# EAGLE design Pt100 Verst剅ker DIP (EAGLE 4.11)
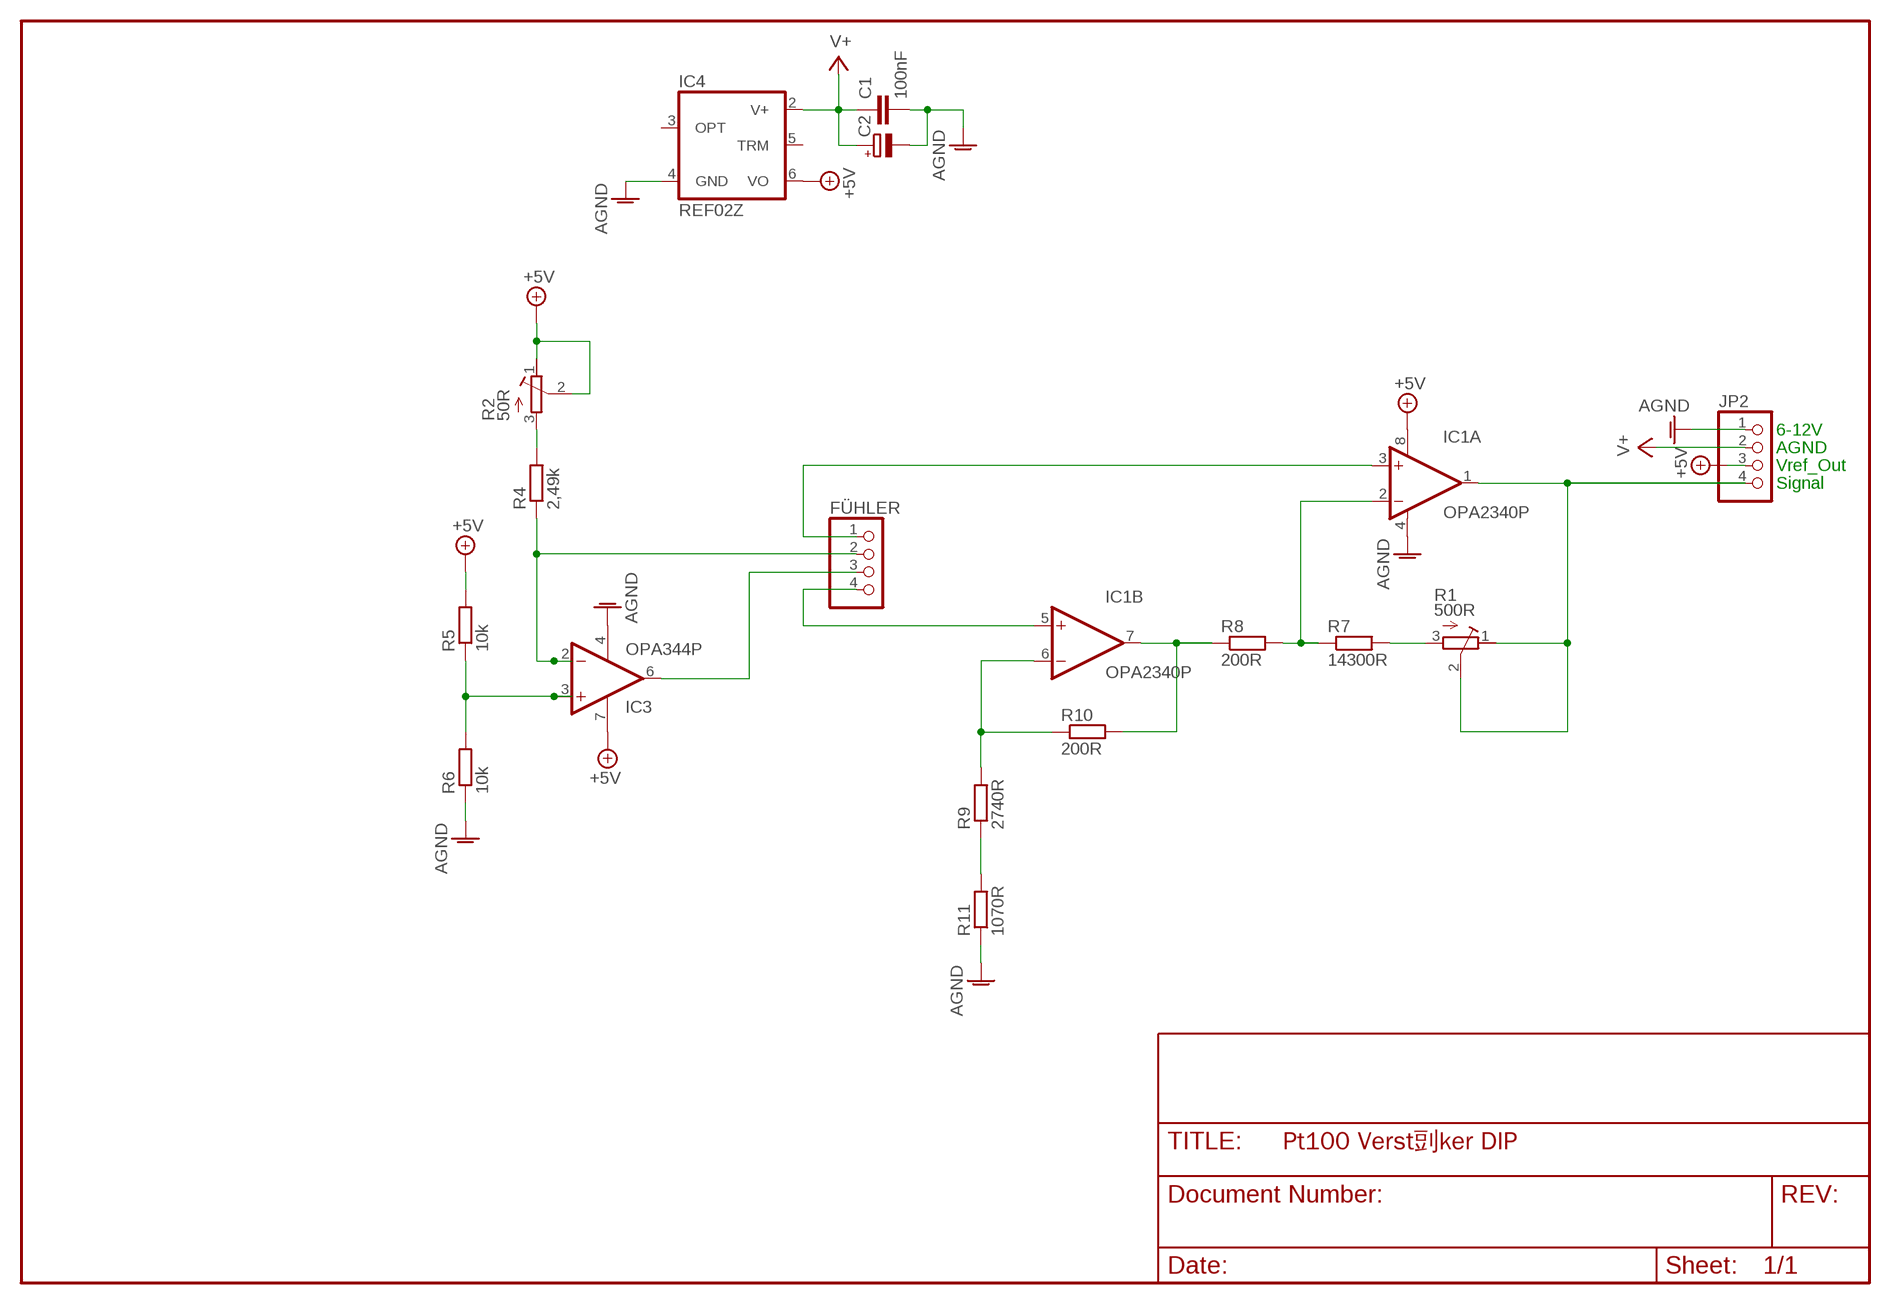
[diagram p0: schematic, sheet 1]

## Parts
C1  100nF  C-EU050-025X075  [C050-025X075]
C2  CPOL-EUE2-5  [E2-5]
FÜHLER  PINHD-1X4  [1X04]
IC1  OPA2340P  [DIL08]
IC3  OPA344P  [DIL08]
IC4  REF02Z  [DIL08]
JP2  PINHD-1X4  [1X04]
R1  500R  R-TRIMM43P  [RTRIM43P]
R2  50R  R-TRIMM43P  [RTRIM43P]
R4  2,49k  R-EU_0207/10  [0207/10]
R5  10k  R-EU_0207/10  [0207/10]
R6  10k  R-EU_0207/10  [0207/10]
R7  14300R  R-EU_0207/10  [0207/10]
R8  200R  R-EU_0207/10  [0207/10]
R9  2740R  R-EU_0207/10  [0207/10]
R10  200R  R-EU_0207/10  [0207/10]
R11  1070R  R-EU_0207/10  [0207/10]

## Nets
+5V: IC1.8(A:V+) IC3.7(V+) IC4.6(VO) JP2.3 R2.1(A) R2.2(S) R5.2
AGND: C1.2 C2.- IC1.4(A:V-) IC3.4(V-) IC4.4(GND) JP2.1 R6.1 R11.1
N$1: R2.3(E) R4.2
N$2: FÜHLER.2 IC3.2(-IN) R4.1
N$3: FÜHLER.3 IC3.6(OUT)
N$4: IC3.3(+IN) R5.1 R6.2
N$5: FÜHLER.4 IC1.5(B:+IN)
N$6: R9.1 R11.2
N$7: IC1.6(B:-IN) R9.2 R10.1
N$8: IC1.7(B:OUT) R8.1 R10.2
N$9: IC1.2(A:-IN) R7.1 R8.2
N$10: R1.3(E) R7.2
N$11: IC1.1(A:OUT) JP2.4 R1.1(A) R1.2(S)
N$12: FÜHLER.1 IC1.3(A:+IN)
V+: C1.1 C2.+ IC4.2(V+) JP2.2
Unconnected: IC4.3(OPT) IC4.5(TRM)

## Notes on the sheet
- 6-12V
- AGND
- Vref_Out
- Signal

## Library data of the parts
C1 = rcl:C-EU: CAPACITOR, European symbol
C2 = rcl:CPOL-EU: POLARIZED CAPACITOR, European symbol
FÜHLER JP2 = pinhead:PINHD-1X4: PIN HEADER
IC1 = burr-brown:OPA2340: Single-Supply, Rail-to-Rail Operational Amplifiers MicroAmplifier(TM) Series; Product Folder:OPA2340
IC3 = linear3:OPA*: Single Operational Amplifier Low Power, Single-Supply, Rail-To-Rail Operational Amplifier Source: http://focus.ti.com/lit/ds/symlink/opa2345.pdf
IC4 = linear:REF02: VOLTAGE REFERENCE
R1 R2 = rcl:R-TRIMM: Trimm resistor
R4-R11 = rcl:R-EU_: RESISTOR, European symbol

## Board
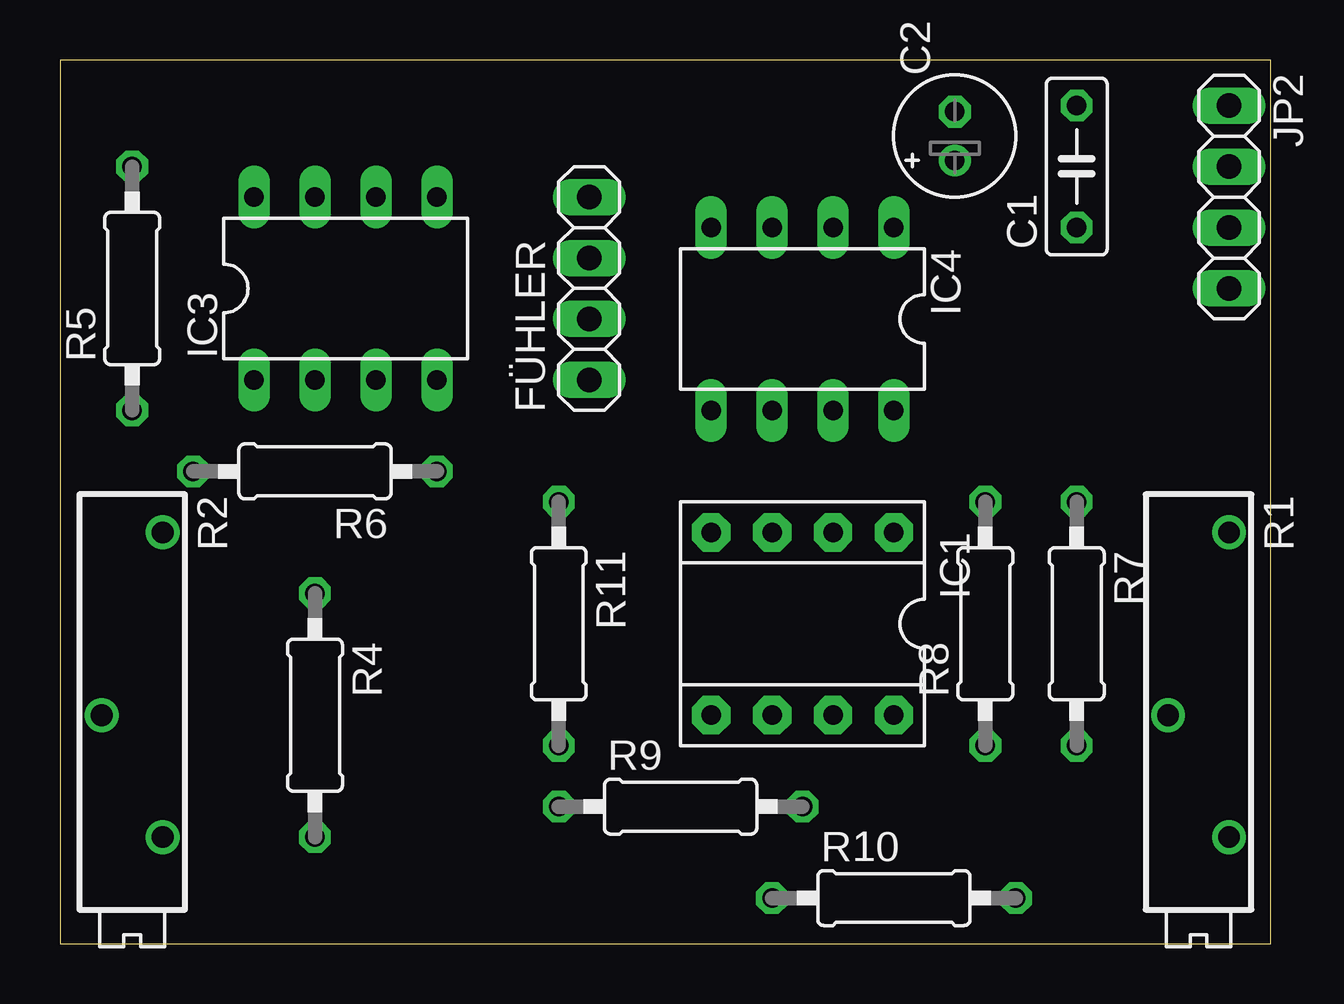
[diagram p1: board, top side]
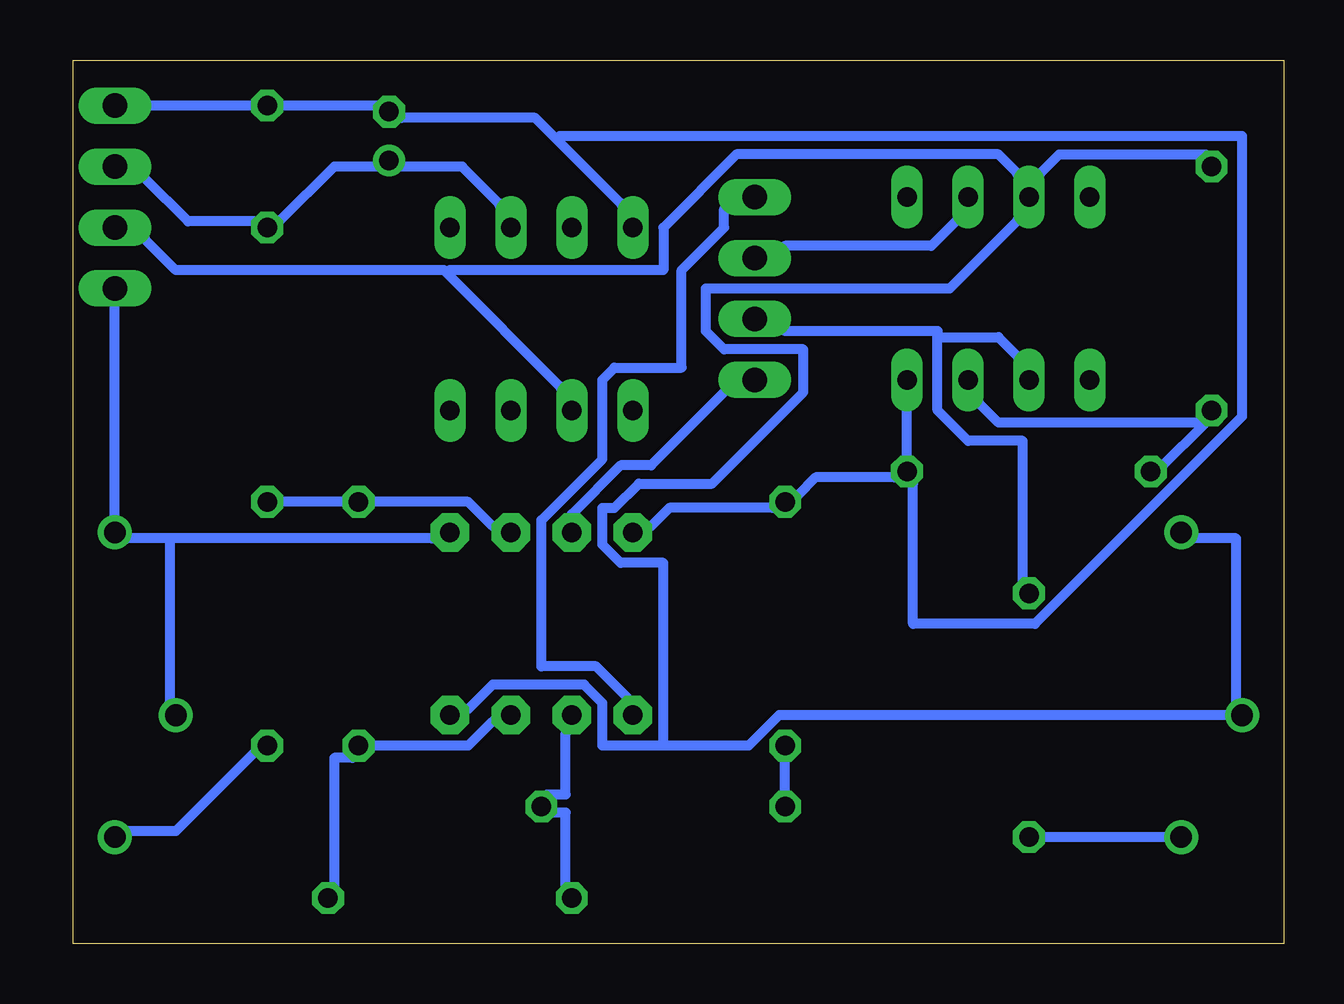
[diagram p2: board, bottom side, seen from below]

Size 50.47 x 36.82 mm. Coordinates in mm from the lower left corner, seen from the top.
Outline: 0,0 50.47,0 50.47,36.82 0,36.82 0,0
Copper layers (1*16): Top 0.035mm / dielectric 1.5mm / Bottom 0.035mm
Design rules "default": minimum track width 16mil, minimum drill 24mil, track to track 8mil, track to pad 8mil, pad to pad 8mil, via to via 8mil, smd to smd 8mil, copper to edge 40mil, drill to drill 8mil, minimum pad ring 10mil, minimum via ring 8mil, stop-mask expansion 4mil, vias tented up to drill 0mil, thermal gap 10mil

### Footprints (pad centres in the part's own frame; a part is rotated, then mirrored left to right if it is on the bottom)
C050-025X075 = drill 0.813 octagon: 1 -2.54,0; 2 2.54,0
E2-5 = drill 0.813 pad 1.27 round: + -1.016,0 | drill 0.813 pad 1.27 octagon: - 1.016,0
1X04 = drill 1.016 long: 1 -3.81,0; 2 -1.27,0; 3 1.27,0; 4 3.81,0
DIL08 = drill 0.813 pad 1.6 octagon: 1 -3.81,-3.81; 2 -1.27,-3.81; 3 1.27,-3.81; 4 3.81,-3.81; 5 3.81,3.81; 6 1.27,3.81; 7 -1.27,3.81; 8 -3.81,3.81
DIL08' = drill 0.813 long: 1 -3.81,-3.81; 2 -1.27,-3.81; 3 1.27,-3.81; 4 3.81,-3.81; 5 3.81,3.81; 6 1.27,3.81; 7 -1.27,3.81; 8 -3.81,3.81
RTRIM43P = drill 0.9 round: 1 -7.62,1.27; 2 0,-1.27; 3 5.08,1.27
0207/10 = drill 0.813 octagon: 1 -5.08,0; 2 5.08,0

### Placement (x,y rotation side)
C1  42.38,32.38 90 top
C2  37.3,33.65 90 top
FÜHLER  22.06,27.3 90 top
IC1  30.95,13.33 180 top
IC3  OPA344P  [DIL08']  11.9,27.3 0 top
IC4  REF02Z  [DIL08']  30.95,26.03 180 top
JP2  48.73,31.11 270 top
R1  47.46,9.52 270 top
R2  3.01,9.52 270 top
R4  10.63,9.52 270 top
R5  3.01,27.3 90 top
R6  10.63,19.68 180 top
R7  42.38,13.33 270 top
R8  38.57,13.33 90 top
R9  25.87,5.71 0 top
R10  34.76,1.9 0 top
R11  20.79,13.33 270 top

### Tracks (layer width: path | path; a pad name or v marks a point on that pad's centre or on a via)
+5V
  Bottom 0.406: R2.1 3.77,16.89 1.99,16.89 1.99,10.03 R2.2 21.04,9.52 22.31,8.25 25.87,8.25 | 25.87,8.25 28.41,8.25 28.41,10.03 29.17,10.79 32.98,10.79 34,9.77 IC1.8 | IC3.7 10.12,32.13 9.36,32.89 3.26,32.89 R5.2 | 34.89,27.93 35.01,28.06 46.19,28.06 47.46,29.33 JP2.3 | 34.89,27.93 30.19,23.24 IC4.6 | IC3.7 11.14,32.13 11.9,32.89 22.82,32.89 25.87,29.84 25.87,28.06 34.76,28.06 34.89,27.93 | 25.87,8.25 25.87,15.87 27.65,15.87 28.41,16.63 28.41,18.16 27.9,18.16 26.89,19.17 23.84,19.17 20.03,22.98 20.03,24.76 23.33,24.76 24.09,25.52 24.09,27.3 13.93,27.3 11.14,30.09 IC3.7
AGND
  Bottom 0.406: R6.1 IC3.4 | R6.1 16.22,19.43 19.52,19.43 20.28,18.66 R11.1 21.3,18.16 25.62,18.16 26.38,17.39 IC1.4 | 30.31,33.52 31.2,34.41 36.79,34.41 C2.- 37.81,34.92 C1.2 JP2.1 | 30.31,33.52 27.65,30.86 IC4.4 | R6.1 15.46,19.17 15.46,13.33 10.38,13.33 1.74,21.97 1.74,33.65 30.19,33.65 30.31,33.52
N$1
  Bottom 0.406: R2.3 R4.2
N$2
  Bottom 0.406: 14.44,25.27 14.44,25.52 20.79,25.52 FÜHLER.2 | 14.44,25.27 14.44,22.22 13.17,20.95 10.88,20.95 10.88,15.11 R4.1 | 14.44,25.27 11.9,25.27 11.14,24.51 IC3.2
N$3
  Bottom 0.406: IC3.6 13.68,30.09 14.69,29.08 20.79,29.08 FÜHLER.3
N$4
  Bottom 0.406: 3.39,21.59 3.26,21.71 R5.1 | 3.39,21.59 5.04,19.93 R6.2 | IC3.3 12.66,22.47 11.9,21.71 3.52,21.71 3.39,21.59
N$5
  Bottom 0.406: FÜHLER.4 23.33,30.6 23.33,29.84 25.11,28.06 25.11,24 27.9,24 28.41,23.49 28.41,20.19 30.95,17.65 30.95,11.55 28.66,11.55 27.39,10.28 IC1.5
N$6
  Bottom 0.406: R9.1 R11.2
N$7
  Bottom 0.406: R10.1 29.93,2.41 29.93,5.46 30.44,5.46 R9.2 30.7,6.22 29.93,6.22 29.93,8.76 IC1.6
N$8
  Bottom 0.406: R10.2 39.59,2.41 39.59,7.74 38.82,7.74 R8.1 34,8.25 32.98,9.27 IC1.7
N$9
  Bottom 0.406: R7.1 R8.2 34,18.41 32.98,17.39 IC1.2
N$10
  Bottom 0.406: R7.2 42.89,8 46.19,4.69 48.22,4.69 R1.3
N$11
  Bottom 0.406: 46.44,16.89 46.44,10.03 R1.2 | 46.44,16.89 48.22,16.89 R1.1 JP2.4 | 46.44,16.89 35.52,16.89 IC1.1
N$12
  Bottom 0.406: FÜHLER.1 23.33,22.98 26.38,19.93 27.65,19.93 29.68,17.9 IC1.3
V+
  Bottom 0.406: IC4.2 32.73,30.86 34.25,32.38 36.79,32.38 C2.+ 37.81,32.38 39.59,32.38 41.87,30.09 C1.1 42.89,30.09 45.68,30.09 47.46,31.87 JP2.2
